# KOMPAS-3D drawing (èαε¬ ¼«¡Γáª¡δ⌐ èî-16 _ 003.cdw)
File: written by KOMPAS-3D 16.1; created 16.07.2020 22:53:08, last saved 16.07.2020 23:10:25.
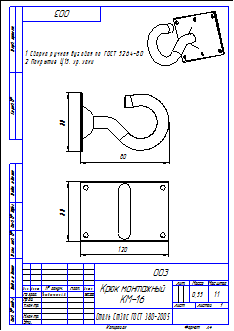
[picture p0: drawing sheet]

Sheet 1: A4, portrait

Title block, sheet 1: name: Крюк монтажный / КМ-16; designation: 003; material: Сталь Ст3пс ГОСТ 380-2005; mass: 0,55; scale: 1:1; sheets: 1; sheet format: A4; stored path: D:\Новая папка\работа\Чертежи\Крюк\Крюк монтажный КМ-16 _ 003.cdw; drawn by: Чередниченко А.В.; drawn by, date: 16.07.2020.

Views: Вид 2, Справа, Вид 3, Вид:1
Referenced files in D:\Новая папка\работа\Чертежи\Крюк\: Крюк монтажный КМ-16.a3d, Основание.m3d, Крюк.m3d
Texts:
  user
  1 Сварка ручная дуговая по ГОСТ 5264-80
  Основание
  Крюк
Dimensions and other numbers on the sheet: 003; 80; 120; 2 Покрытие Ц15. хр. хаки; 1:1; 1; 0,55; 16.07.2020.; 003-; 002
